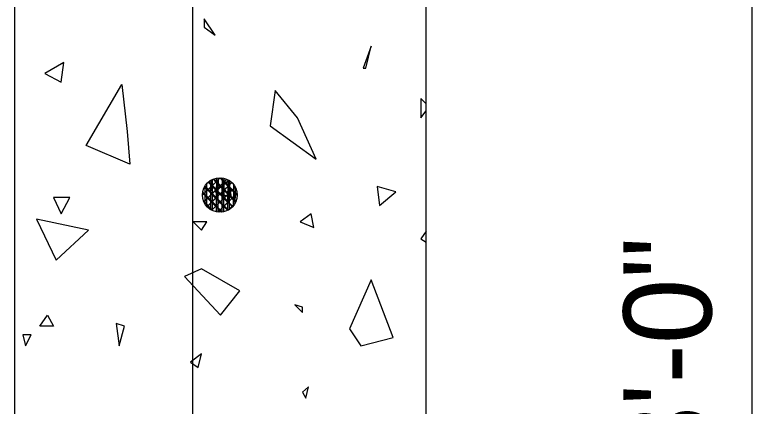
# Model space of a CAD drawing. Extents: x 8.6 to 15.9, y 6.4 to 16.6.
# Drawn here: x 11.677 to 12.179, y 10.776 to 11.043 of the extents above; entities that cross this region are included whole.
import ezdxf

# ---------------------------------------------------------------- set-up
doc = ezdxf.new("R2010")
doc.units = 0
for name, color, linetype in [('DETL-DIMS', 7, 'Continuous'), ('DETL-LINE', 7, 'Continuous'), ('DETL-NOTE', 7, 'Continuous'), ('DETL-PATT', 7, 'Continuous')]:
    doc.layers.add(name, color=color, linetype=linetype)

msp = doc.modelspace()

# ---------------------------------------------------------------- linework, layer by layer
at = {"layer": 'DETL-DIMS'}
msp.add_line((12.17919, 9.84944), (12.17919, 11.92421), dxfattribs=at)
at = {"layer": 'DETL-LINE'}
for p, q in [((11.95697, 9.51644), (11.95697, 12.84203)), ((11.67679, 9.84944), (11.67679, 12.60906)), ((11.79801, 9.91432), (11.79801, 11.77888)), ((11.81527, 10.93029), (11.80638, 10.92155)), ((11.81797, 10.92751), (11.80905, 10.91877)), ((11.81038, 10.91655), (11.81049, 10.92903)), ((11.81149, 10.91655), (11.8116, 10.92903)), ((11.82075, 10.93025), (11.81182, 10.92151)), ((11.82194, 10.92058), (11.81319, 10.92947)), ((11.82223, 10.92103), (11.81345, 10.92992)), ((11.81427, 10.91651), (11.81438, 10.92899)), ((11.82345, 10.92747), (11.81457, 10.91873)), ((11.81538, 10.91651), (11.81545, 10.92899)), ((11.81816, 10.91647), (11.81827, 10.92895)), ((11.82745, 10.92055), (11.81871, 10.92944)), ((11.82771, 10.92095), (11.81897, 10.92984)), ((11.81927, 10.91647), (11.81934, 10.92895)), ((11.82205, 10.91644), (11.82216, 10.92892)), ((11.82312, 10.91644), (11.82323, 10.92892)), ((11.81519, 10.92477), (11.80631, 10.91603)), ((11.80757, 10.91269), (11.80768, 10.92518)), ((11.81638, 10.91514), (11.80764, 10.92406)), ((11.81668, 10.91555), (11.80794, 10.92444)), ((11.81034, 10.91266), (11.81045, 10.92514)), ((11.81916, 10.91788), (11.81042, 10.92677)), ((11.81945, 10.91829), (11.81071, 10.92718)), ((11.81145, 10.91266), (11.81157, 10.92514)), ((11.82071, 10.92473), (11.81179, 10.91599)), ((11.8219, 10.9151), (11.81316, 10.92403)), ((11.82219, 10.91551), (11.81342, 10.9244)), ((11.81423, 10.91262), (11.81434, 10.9251)), ((11.81534, 10.91262), (11.81545, 10.9251)), ((11.82468, 10.91781), (11.81594, 10.92669)), ((11.82497, 10.91825), (11.81619, 10.92714)), ((11.82619, 10.92469), (11.81731, 10.91595)), ((11.81812, 10.91258), (11.81823, 10.92506)), ((11.81923, 10.91258), (11.81934, 10.92506)), ((11.82201, 10.91258), (11.82212, 10.92503)), ((11.82312, 10.91255), (11.82323, 10.92503)), ((11.81364, 10.91244), (11.80486, 10.92132)), ((11.8139, 10.91284), (11.80516, 10.92173)), ((11.81634, 10.90966), (11.8076, 10.91855)), ((11.81664, 10.91006), (11.8079, 10.91899)), ((11.81794, 10.92203), (11.80901, 10.91325)), ((11.81912, 10.9124), (11.81038, 10.92129)), ((11.81942, 10.91277), (11.81068, 10.92166)), ((11.82068, 10.91925), (11.81175, 10.91047)), ((11.82186, 10.90962), (11.81312, 10.91851)), ((11.82216, 10.90999), (11.81338, 10.91892)), ((11.81419, 10.90873), (11.81431, 10.92121)), ((11.82342, 10.92199), (11.81453, 10.91321)), ((11.81531, 10.90873), (11.81542, 10.92121)), ((11.82464, 10.91236), (11.8159, 10.92125)), ((11.82494, 10.91273), (11.81616, 10.92162)), ((11.82616, 10.91921), (11.81727, 10.91044)), ((11.81808, 10.90869), (11.81819, 10.92118)), ((11.81919, 10.90869), (11.81931, 10.92118))]:
    msp.add_line(p, q, dxfattribs=at)
for points in [[(11.81249, 10.92755), (11.80479, 10.91999)], [(11.8076, 10.91658), (11.80768, 10.92781)], [(11.80764, 10.92047), (11.80768, 10.92781)], [(11.80764, 10.92436), (11.80768, 10.92781)], [(11.81645, 10.92066), (11.80853, 10.92869)], [(11.81375, 10.92344), (11.80853, 10.92869)], [(11.81101, 10.92621), (11.80853, 10.92869)], [(11.81671, 10.92106), (11.80894, 10.92899)], [(11.81401, 10.92384), (11.80894, 10.92899)], [(11.81127, 10.92662), (11.80894, 10.92899)], [(11.81679, 10.93181), (11.80912, 10.92429)], [(11.81042, 10.92044), (11.81049, 10.93014)], [(11.81045, 10.92432), (11.81049, 10.93014)], [(11.81049, 10.92821), (11.81049, 10.93014)], [(11.81149, 10.92044), (11.8116, 10.93073)], [(11.81153, 10.92432), (11.8116, 10.93073)], [(11.81157, 10.92821), (11.8116, 10.93073)], [(11.81679, 10.93181), (11.8119, 10.92699)], [(11.81923, 10.92336), (11.8119, 10.93084)], [(11.81649, 10.92614), (11.8119, 10.93084)], [(11.81379, 10.92892), (11.8119, 10.93084)], [(11.81949, 10.92381), (11.81238, 10.93106)], [(11.81679, 10.92658), (11.81238, 10.93106)], [(11.81405, 10.92932), (11.81238, 10.93106)], [(11.81431, 10.9204), (11.81438, 10.93162)], [(11.81434, 10.92429), (11.81438, 10.93162)], [(11.81438, 10.92818), (11.81438, 10.93162)], [(11.82131, 10.93077), (11.8146, 10.92421)], [(11.81538, 10.9204), (11.81549, 10.93177)], [(11.81542, 10.92429), (11.81549, 10.93177)], [(11.81545, 10.92818), (11.81549, 10.93177)], [(11.82471, 10.92332), (11.81642, 10.93181)], [(11.82201, 10.9261), (11.81642, 10.93181)], [(11.81927, 10.92888), (11.81642, 10.93181)], [(11.81653, 10.93166), (11.81642, 10.93181)], [(11.82501, 10.92373), (11.81708, 10.93181)], [(11.82227, 10.92651), (11.81708, 10.93181)], [(11.81957, 10.92929), (11.81708, 10.93181)], [(11.8246, 10.92858), (11.81734, 10.92144)], [(11.81819, 10.92036), (11.81827, 10.93166)], [(11.81823, 10.92425), (11.81827, 10.93166)], [(11.81827, 10.92814), (11.81827, 10.93166)], [(11.81927, 10.92036), (11.81938, 10.93144)], [(11.81931, 10.92425), (11.81938, 10.93144)], [(11.81934, 10.92814), (11.81938, 10.93144)], [(11.82208, 10.92032), (11.82216, 10.93036)], [(11.82212, 10.92421), (11.82216, 10.93036)], [(11.82212, 10.9281), (11.82216, 10.93036)], [(11.82316, 10.92032), (11.82327, 10.92969)], [(11.82319, 10.92421), (11.82327, 10.92969)], [(11.82323, 10.9281), (11.82327, 10.92969)], [(11.80971, 10.92481), (11.80479, 10.91999)], [(11.81368, 10.91792), (11.80616, 10.92558)], [(11.81097, 10.92069), (11.80616, 10.92558)], [(11.80823, 10.92347), (11.80616, 10.92558)], [(11.81394, 10.91832), (11.80642, 10.92603)], [(11.81123, 10.9211), (11.80642, 10.92603)], [(11.80849, 10.92388), (11.80642, 10.92603)], [(11.80645, 10.91403), (11.80657, 10.92518)], [(11.80649, 10.91658), (11.80657, 10.92629)], [(11.80653, 10.92047), (11.80657, 10.92629)], [(11.80657, 10.92436), (11.80657, 10.92629)], [(11.82723, 10.91521), (11.81868, 10.92395)], [(11.82745, 10.91573), (11.81894, 10.92436)], [(11.82697, 10.92544), (11.82008, 10.91866)], [(11.82827, 10.91973), (11.82142, 10.92666)], [(11.82827, 10.9204), (11.82171, 10.92706)], [(11.82827, 10.91973), (11.82416, 10.92392)], [(11.82827, 10.9204), (11.82445, 10.92429)], [(11.8259, 10.91299), (11.82601, 10.92499)], [(11.82594, 10.91644), (11.82601, 10.92699)], [(11.82597, 10.92032), (11.82601, 10.92699)], [(11.82601, 10.92421), (11.82601, 10.92699)], [(11.82701, 10.9164), (11.82712, 10.92518)], [(11.82701, 10.91473), (11.82708, 10.92499)], [(11.82705, 10.92029), (11.82712, 10.92518)], [(11.82708, 10.92418), (11.82712, 10.92518)], [(11.80694, 10.92214), (11.80479, 10.91999)], [(11.8109, 10.91518), (11.80486, 10.92132)], [(11.80819, 10.91795), (11.80486, 10.92132)], [(11.80545, 10.92073), (11.80486, 10.92132)], [(11.81116, 10.91562), (11.80494, 10.92199)], [(11.80845, 10.9184), (11.80494, 10.92199)], [(11.80575, 10.92118), (11.80494, 10.92199)], [(11.81242, 10.92206), (11.80571, 10.91547)], [(11.80964, 10.91936), (11.80571, 10.91547)], [(11.80645, 10.91403), (11.80653, 10.92129)], [(11.80645, 10.91403), (11.80649, 10.9174)], [(11.80757, 10.91251), (11.80764, 10.92129)], [(11.80757, 10.91251), (11.8076, 10.9174)], [(11.81516, 10.91929), (11.80786, 10.91214)], [(11.81031, 10.9101), (11.81042, 10.92125)], [(11.81031, 10.9101), (11.81038, 10.91736)], [(11.81142, 10.90947), (11.81153, 10.92125)], [(11.81142, 10.90947), (11.81149, 10.91736)], [(11.81419, 10.90855), (11.81427, 10.91732)], [(11.81531, 10.90836), (11.81538, 10.91732)], [(11.82505, 10.91192), (11.8186, 10.91847)], [(11.82534, 10.91232), (11.8189, 10.91888)], [(11.82819, 10.92121), (11.82005, 10.91318)], [(11.82723, 10.91521), (11.82138, 10.92118)], [(11.82745, 10.91573), (11.82168, 10.92158)], [(11.82197, 10.90966), (11.82208, 10.92114)], [(11.82819, 10.92121), (11.82282, 10.91588)], [(11.82308, 10.91032), (11.82319, 10.92114)], [(11.8259, 10.91299), (11.82597, 10.9211)], [(11.82701, 10.91473), (11.82708, 10.9211)], [(11.81201, 10.90921), (11.8056, 10.91577)], [(11.81112, 10.9101), (11.8056, 10.91577)], [(11.80838, 10.91288), (11.8056, 10.91577)], [(11.80571, 10.91566), (11.8056, 10.91577)], [(11.80686, 10.91662), (11.80571, 10.91547)], [(11.81075, 10.90981), (11.80619, 10.91444)], [(11.81075, 10.90981), (11.80619, 10.91444)], [(11.80812, 10.91251), (11.80619, 10.91444)], [(11.81075, 10.90981), (11.80757, 10.91306)], [(11.81238, 10.91658), (11.80786, 10.91214)], [(11.8096, 10.91384), (11.80786, 10.91214)], [(11.81201, 10.90921), (11.80786, 10.91347)], [(11.81764, 10.90836), (11.81034, 10.91577)], [(11.81819, 10.90844), (11.81064, 10.91621)], [(11.8179, 10.91651), (11.81097, 10.90969)], [(11.81512, 10.91381), (11.81097, 10.90969)], [(11.81764, 10.90836), (11.81305, 10.91299)], [(11.81819, 10.90844), (11.81334, 10.91344)], [(11.82338, 10.91647), (11.81516, 10.9084)], [(11.8206, 10.91373), (11.81516, 10.9084)], [(11.8219, 10.90958), (11.81582, 10.91573)], [(11.82231, 10.90984), (11.81612, 10.91614)], [(11.81808, 10.90844), (11.81816, 10.91729)], [(11.81919, 10.90862), (11.81927, 10.91729)], [(11.82197, 10.90966), (11.82205, 10.91725)], [(11.82686, 10.91444), (11.82197, 10.90962)], [(11.82608, 10.91369), (11.82197, 10.90962)], [(11.82686, 10.91444), (11.82275, 10.9104)], [(11.82308, 10.91032), (11.82316, 10.91725)], [(11.82686, 10.91444), (11.82553, 10.9131)], [(11.8259, 10.91299), (11.82594, 10.91721)], [(11.82701, 10.91473), (11.82705, 10.91721)], [(11.81075, 10.90981), (11.81027, 10.91029)], [(11.81201, 10.90921), (11.81057, 10.91069)], [(11.81234, 10.91106), (11.81097, 10.90969)], [(11.81782, 10.91103), (11.81516, 10.9084)], [(11.82331, 10.91095), (11.82197, 10.90962)]]:
    msp.add_lwpolyline(points, dxfattribs=at)
msp.add_circle((11.81653, 10.92006), 0.01177, dxfattribs=at)
at = {"layer": 'DETL-PATT'}
for points in [[(11.80579, 11.04006), (11.80579, 11.03429), (11.81334, 11.02895)], [(11.91423, 11.00629), (11.91601, 11.00629), (11.91957, 11.0214)], [(11.69734, 11.00273), (11.70845, 10.99695), (11.71023, 11.01029)], [(11.75334, 10.96318), (11.75512, 10.94095), (11.72534, 10.95384), (11.74979, 10.99518)], [(11.85423, 10.99118), (11.85068, 10.96718), (11.88223, 10.94451), (11.86934, 10.97251)], [(11.82268, 10.92984), (11.81334, 10.92229), (11.82445, 10.91829)], [(11.92357, 10.92584), (11.92534, 10.91295), (11.93645, 10.92229)], [(11.70312, 10.91829), (11.70845, 10.90718), (11.71423, 10.91829)], [(11.69157, 10.90362), (11.7049, 10.87562), (11.72712, 10.89606)], [(11.87112, 10.90184), (11.88045, 10.89784), (11.87868, 10.90718)], [(11.79823, 10.90184), (11.80401, 10.89606), (11.80757, 10.90184)], [(11.79245, 10.86451), (11.8169, 10.83829), (11.83023, 10.85473), (11.80401, 10.86984)], [(11.91245, 10.8174), (11.93468, 10.82318), (11.91957, 10.86229), (11.9049, 10.82895)], [(11.8729, 10.84362), (11.86757, 10.8454), (11.8729, 10.84006)], [(11.69912, 10.83829), (11.70312, 10.83073), (11.69379, 10.83073)], [(11.74579, 10.83251), (11.74801, 10.8174), (11.75157, 10.83073)], [(11.68223, 10.82495), (11.68401, 10.8174), (11.68801, 10.82495)], [(11.79645, 10.80629), (11.80179, 10.80273), (11.80401, 10.81206)], [(11.8769, 10.7894), (11.8729, 10.78584), (11.87512, 10.78184)]]:
    msp.add_lwpolyline(points, close=True, dxfattribs=at)
for points in [[(11.95697, 10.98221), (11.95334, 10.98584), (11.95334, 10.97251), (11.95697, 10.97725)], [(11.95697, 10.89551), (11.95334, 10.89029), (11.95697, 10.88806)]]:
    msp.add_lwpolyline(points, dxfattribs=at)

# ---------------------------------------------------------------- texts
at = {"layer": 'DETL-NOTE'}
msp.add_text('8\'-0"', height=0.06, rotation=90, dxfattribs=at).set_placement((12.15142, 10.73188))

doc.saveas('drawing.dxf')
